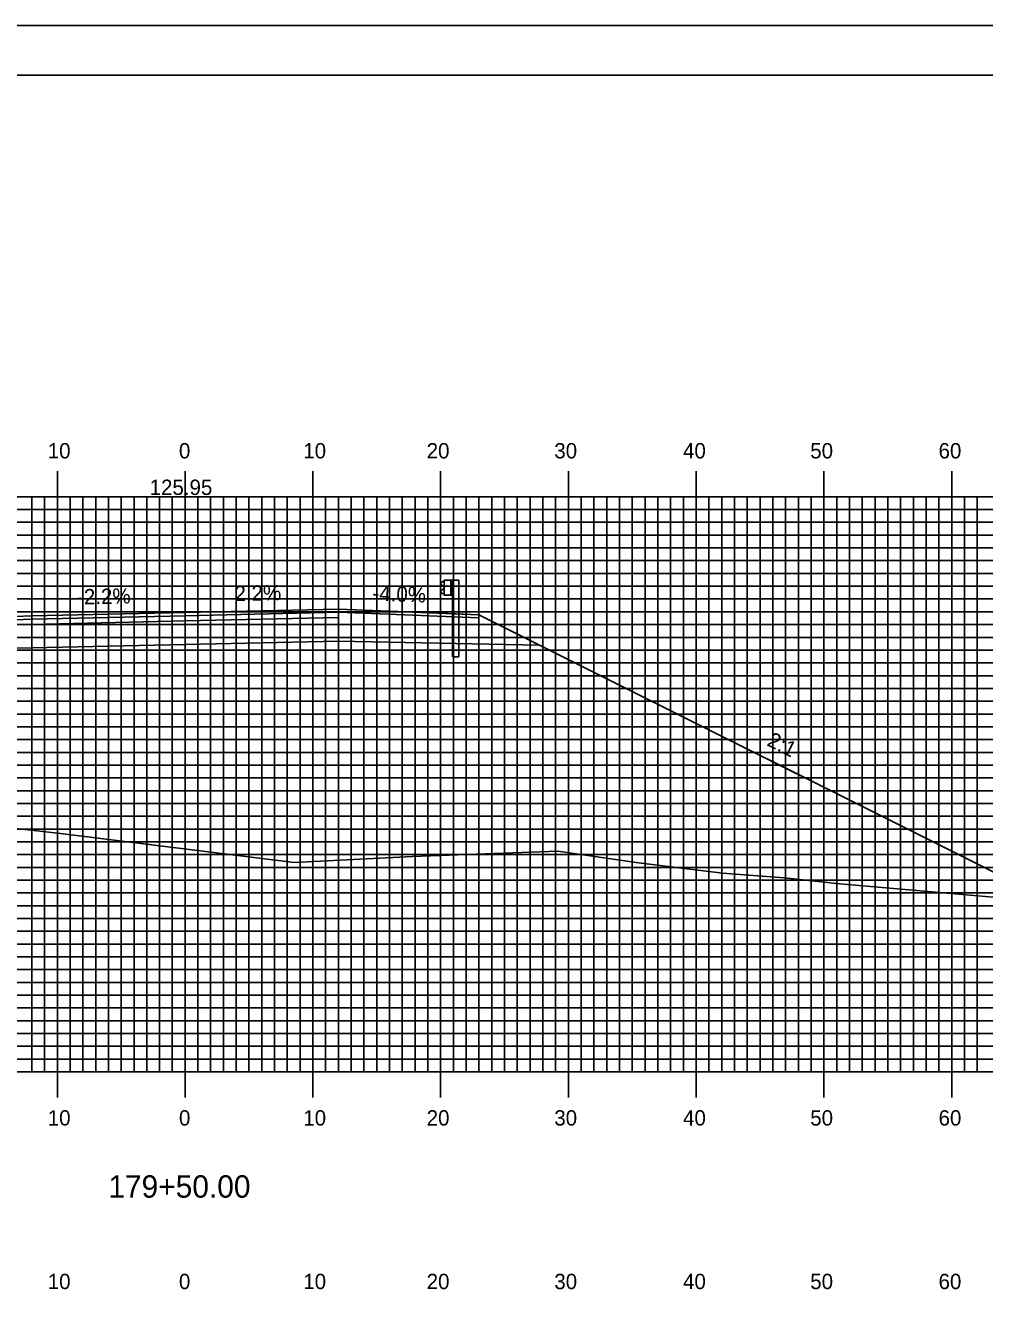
# Model space of a CAD drawing. Extents: x 1785402 to 1785745, y 442591 to 442811.
# Drawn here: x 1785555 to 1785630.1, y 442711.2 to 442810.5 of the extents above; entities that cross this region are included whole.
import ezdxf

# ---------------------------------------------------------------- set-up
doc = ezdxf.new("R2010")
doc.units = 0
for name, color, linetype in [('ANNOTATION', 7, 'Continuous'), ('BORDER', 7, 'Continuous'), ('D_Guardrail_Beam_Rt', 7, 'Continuous'), ('D_Roadway_Centerline', 7, 'Continuous'), ('D_Roadway_Centerline_Text', 7, 'Continuous'), ('D_Roadway_Edge_Shoulder', 7, 'Continuous'), ('D_Roadway_Edge_TW', 7, 'Continuous'), ('D_Roadway_Pavement', 7, 'Continuous'), ('D_Roadway_SlopeLines', 7, 'Continuous'), ('D_Roadway_SubGrade', 7, 'Continuous'), ('H_V ANNOTATION', 7, 'Continuous'), ('MAJOR', 7, 'Continuous'), ('MINOR', 7, 'Continuous'), ('PLOT BOUNDARY', 7, 'Continuous'), ('S_Roadway_Centerline', 7, 'Continuous')]:
    doc.layers.add(name, color=color, linetype=linetype)

msp = doc.modelspace()

# ---------------------------------------------------------------- linework, layer by layer
at = {"layer": 'BORDER'}
msp.add_lwpolyline([(1785417.939, 442596.665), (1785737.939, 442596.665), (1785737.939, 442806.665), (1785417.939, 442806.665)], close=True, dxfattribs=at)
at = {"layer": 'D_Guardrail_Beam_Rt'}
for p, q in [((1785587.72, 442767.033), (1785587.576, 442766.933)), ((1785587.576, 442766.79), (1785587.771, 442766.654)), ((1785587.809, 442767.054), (1785587.735, 442767.04)), ((1785587.809, 442767.138), (1785588.497, 442767.138)), ((1785587.809, 442765.971), (1785587.809, 442767.138)), ((1785588.33, 442767.138), (1785588.33, 442765.971)), ((1785588.434, 442767.138), (1785588.434, 442765.971)), ((1785588.497, 442767.138), (1785588.968, 442767.138)), ((1785588.497, 442767.138), (1785588.497, 442765.971)), ((1785588.968, 442767.138), (1785588.968, 442761.138)), ((1785587.771, 442766.455), (1785587.576, 442766.319)), ((1785587.576, 442766.176), (1785587.72, 442766.076)), ((1785587.735, 442766.069), (1785587.809, 442766.054)), ((1785587.805, 442766.589), (1785587.805, 442766.519)), ((1785588.497, 442765.971), (1785587.809, 442765.971)), ((1785588.476, 442761.138), (1785588.476, 442765.971)), ((1785588.476, 442761.138), (1785588.968, 442761.138))]:
    msp.add_line(p, q, dxfattribs=at)
for centre, major_axis, start_param, end_param in [((1785587.626, 442766.861), (-0.0877, 0), 5.323254, 7.243116), ((1785587.743, 442766.999), (-0.0417, 0), 4.907132, 5.323254), ((1785587.726, 442766.589), (0.0789, 0), 0, 0.959931), ((1785587.626, 442766.247), (-0.0877, 0), 5.323254, 7.243116), ((1785587.743, 442766.11), (-0.0417, 0), 0.959931, 1.376053), ((1785587.726, 442766.519), (0.0789, 0), 5.323254, 6.283185)]:
    msp.add_ellipse(centre, major_axis=major_axis, ratio=0.995501, start_param=start_param, end_param=end_param, dxfattribs=at)
at = {"layer": 'D_Roadway_Centerline'}
msp.add_lwpolyline([(1785504.216, 442750.585), (1785535.539, 442761.026), (1785537.365, 442761.483), (1785547.539, 442764.026), (1785555.539, 442764.346), (1785567.539, 442764.61), (1785579.539, 442764.874), (1785587.539, 442764.554), (1785590.539, 442764.434), (1785595.289, 442762.059), (1785635.591, 442741.908)], dxfattribs=at)
at = {"layer": 'D_Roadway_Edge_Shoulder'}
for points in [[(1785579.539, 442764.874), (1785587.539, 442764.554), (1785587.539, 442764.554), (1785590.539, 442764.434), (1785590.539, 442764.184), (1785579.539, 442764.624)], [(1785579.539, 442764.874), (1785590.539, 442764.434), (1785590.539, 442764.184), (1785579.539, 442764.624)], [(1785555.539, 442764.346), (1785547.539, 442764.026), (1785547.539, 442763.776), (1785555.539, 442764.096)]]:
    msp.add_lwpolyline(points, close=True, dxfattribs=at)
at = {"layer": 'D_Roadway_Edge_TW'}
msp.add_lwpolyline([(1785555.539, 442764.096), (1785555.539, 442764.346), (1785567.539, 442764.61), (1785579.539, 442764.874), (1785579.539, 442764.624), (1785567.539, 442764.36)], close=True, dxfattribs=at)
at = {"layer": 'D_Roadway_Pavement'}
msp.add_lwpolyline([(1785555.539, 442763.68), (1785555.539, 442764.096), (1785567.539, 442764.36), (1785579.539, 442764.624), (1785579.539, 442764.208), (1785567.539, 442763.944)], close=True, dxfattribs=at)
at = {"layer": 'D_Roadway_SlopeLines'}
msp.add_lwpolyline([(1785590.539, 442764.434), (1785635.591, 442741.908)], dxfattribs=at)
at = {"layer": 'D_Roadway_SubGrade'}
for points in [[(1785555.539, 442761.846), (1785537.365, 442761.483), (1785547.539, 442764.026), (1785547.539, 442763.776), (1785555.539, 442764.096), (1785567.539, 442764.36), (1785579.539, 442764.624), (1785590.539, 442764.184), (1785590.539, 442764.434), (1785595.289, 442762.059), (1785579.539, 442762.374), (1785567.539, 442762.11)], [(1785555.539, 442761.846), (1785537.365, 442761.483), (1785547.539, 442764.026), (1785547.539, 442763.776), (1785555.539, 442764.096)], [(1785555.539, 442761.846), (1785555.539, 442764.096), (1785567.539, 442764.36), (1785579.539, 442764.624), (1785579.539, 442762.374), (1785567.539, 442762.11)], [(1785579.539, 442764.624), (1785590.539, 442764.184), (1785590.539, 442764.434), (1785595.289, 442762.059), (1785579.539, 442762.374)]]:
    msp.add_lwpolyline(points, close=True, dxfattribs=at)
at = {"layer": 'MAJOR'}
for p, q in [((1785557.539, 442775.669), (1785557.539, 442773.665)), ((1785567.539, 442775.669), (1785567.539, 442773.665)), ((1785577.539, 442775.669), (1785577.539, 442773.665)), ((1785587.539, 442775.669), (1785587.539, 442773.665)), ((1785597.539, 442775.669), (1785597.539, 442773.665)), ((1785607.539, 442775.669), (1785607.539, 442773.665)), ((1785617.539, 442775.669), (1785617.539, 442773.665)), ((1785627.539, 442775.669), (1785627.539, 442773.665)), ((1785427.539, 442773.665), (1785707.539, 442773.665)), ((1785427.539, 442773.665), (1785707.539, 442773.665)), ((1785557.539, 442728.665), (1785557.539, 442773.665)), ((1785567.539, 442728.665), (1785567.539, 442773.665)), ((1785577.539, 442728.665), (1785577.539, 442773.665)), ((1785587.539, 442728.665), (1785587.539, 442773.665)), ((1785597.539, 442728.665), (1785597.539, 442773.665)), ((1785607.539, 442728.665), (1785607.539, 442773.665)), ((1785617.539, 442728.665), (1785617.539, 442773.665)), ((1785627.539, 442728.665), (1785627.539, 442773.665)), ((1785427.539, 442768.665), (1785707.539, 442768.665)), ((1785427.539, 442763.665), (1785707.539, 442763.665)), ((1785427.539, 442758.665), (1785707.539, 442758.665)), ((1785427.539, 442753.665), (1785707.539, 442753.665)), ((1785427.539, 442748.665), (1785707.539, 442748.665)), ((1785427.539, 442743.665), (1785707.539, 442743.665)), ((1785427.539, 442738.665), (1785707.539, 442738.665)), ((1785427.539, 442733.665), (1785707.539, 442733.665)), ((1785427.539, 442728.665), (1785707.539, 442728.665)), ((1785427.539, 442728.665), (1785707.539, 442728.665)), ((1785557.539, 442726.661), (1785557.539, 442728.665)), ((1785567.539, 442726.661), (1785567.539, 442728.665)), ((1785577.539, 442726.661), (1785577.539, 442728.665)), ((1785587.539, 442726.661), (1785587.539, 442728.665)), ((1785597.539, 442726.661), (1785597.539, 442728.665)), ((1785607.539, 442726.661), (1785607.539, 442728.665)), ((1785617.539, 442726.661), (1785617.539, 442728.665)), ((1785627.539, 442726.661), (1785627.539, 442728.665))]:
    msp.add_line(p, q, dxfattribs=at)
at = {"layer": 'MINOR'}
for p, q in [((1785555.539, 442728.665), (1785555.539, 442773.665)), ((1785556.539, 442728.665), (1785556.539, 442773.665)), ((1785558.539, 442728.665), (1785558.539, 442773.665)), ((1785559.539, 442728.665), (1785559.539, 442773.665)), ((1785560.539, 442728.665), (1785560.539, 442773.665)), ((1785561.539, 442728.665), (1785561.539, 442773.665)), ((1785562.539, 442728.665), (1785562.539, 442773.665)), ((1785563.539, 442728.665), (1785563.539, 442773.665)), ((1785564.539, 442728.665), (1785564.539, 442773.665)), ((1785565.539, 442728.665), (1785565.539, 442773.665)), ((1785566.539, 442728.665), (1785566.539, 442773.665)), ((1785568.539, 442728.665), (1785568.539, 442773.665)), ((1785569.539, 442728.665), (1785569.539, 442773.665)), ((1785570.539, 442728.665), (1785570.539, 442773.665)), ((1785571.539, 442728.665), (1785571.539, 442773.665)), ((1785572.539, 442728.665), (1785572.539, 442773.665)), ((1785573.539, 442728.665), (1785573.539, 442773.665)), ((1785574.539, 442728.665), (1785574.539, 442773.665)), ((1785575.539, 442728.665), (1785575.539, 442773.665)), ((1785576.539, 442728.665), (1785576.539, 442773.665)), ((1785578.539, 442728.665), (1785578.539, 442773.665)), ((1785579.539, 442728.665), (1785579.539, 442773.665)), ((1785580.539, 442728.665), (1785580.539, 442773.665)), ((1785581.539, 442728.665), (1785581.539, 442773.665)), ((1785582.539, 442728.665), (1785582.539, 442773.665)), ((1785583.539, 442728.665), (1785583.539, 442773.665)), ((1785584.539, 442728.665), (1785584.539, 442773.665)), ((1785585.539, 442728.665), (1785585.539, 442773.665)), ((1785586.539, 442728.665), (1785586.539, 442773.665)), ((1785588.539, 442728.665), (1785588.539, 442773.665)), ((1785589.539, 442728.665), (1785589.539, 442773.665)), ((1785590.539, 442728.665), (1785590.539, 442773.665)), ((1785591.539, 442728.665), (1785591.539, 442773.665)), ((1785592.539, 442728.665), (1785592.539, 442773.665)), ((1785593.539, 442728.665), (1785593.539, 442773.665)), ((1785594.539, 442728.665), (1785594.539, 442773.665)), ((1785595.539, 442728.665), (1785595.539, 442773.665)), ((1785596.539, 442728.665), (1785596.539, 442773.665)), ((1785598.539, 442728.665), (1785598.539, 442773.665)), ((1785599.539, 442728.665), (1785599.539, 442773.665)), ((1785600.539, 442728.665), (1785600.539, 442773.665)), ((1785601.539, 442728.665), (1785601.539, 442773.665)), ((1785602.539, 442728.665), (1785602.539, 442773.665)), ((1785603.539, 442728.665), (1785603.539, 442773.665)), ((1785604.539, 442728.665), (1785604.539, 442773.665)), ((1785605.539, 442728.665), (1785605.539, 442773.665)), ((1785606.539, 442728.665), (1785606.539, 442773.665)), ((1785608.539, 442728.665), (1785608.539, 442773.665)), ((1785609.539, 442728.665), (1785609.539, 442773.665)), ((1785610.539, 442728.665), (1785610.539, 442773.665)), ((1785611.539, 442728.665), (1785611.539, 442773.665)), ((1785612.539, 442728.665), (1785612.539, 442773.665)), ((1785613.539, 442728.665), (1785613.539, 442773.665)), ((1785614.539, 442728.665), (1785614.539, 442773.665)), ((1785615.539, 442728.665), (1785615.539, 442773.665)), ((1785616.539, 442728.665), (1785616.539, 442773.665)), ((1785618.539, 442728.665), (1785618.539, 442773.665)), ((1785619.539, 442728.665), (1785619.539, 442773.665)), ((1785620.539, 442728.665), (1785620.539, 442773.665)), ((1785621.539, 442728.665), (1785621.539, 442773.665)), ((1785622.539, 442728.665), (1785622.539, 442773.665)), ((1785623.539, 442728.665), (1785623.539, 442773.665)), ((1785624.539, 442728.665), (1785624.539, 442773.665)), ((1785625.539, 442728.665), (1785625.539, 442773.665)), ((1785626.539, 442728.665), (1785626.539, 442773.665)), ((1785628.539, 442728.665), (1785628.539, 442773.665)), ((1785629.539, 442728.665), (1785629.539, 442773.665)), ((1785427.539, 442772.665), (1785707.539, 442772.665)), ((1785427.539, 442771.665), (1785707.539, 442771.665)), ((1785427.539, 442770.665), (1785707.539, 442770.665)), ((1785427.539, 442769.665), (1785707.539, 442769.665)), ((1785427.539, 442767.665), (1785707.539, 442767.665)), ((1785427.539, 442766.665), (1785707.539, 442766.665)), ((1785427.539, 442765.665), (1785707.539, 442765.665)), ((1785427.539, 442764.665), (1785707.539, 442764.665)), ((1785427.539, 442762.665), (1785707.539, 442762.665)), ((1785427.539, 442761.665), (1785707.539, 442761.665)), ((1785427.539, 442760.665), (1785707.539, 442760.665)), ((1785427.539, 442759.665), (1785707.539, 442759.665)), ((1785427.539, 442757.665), (1785707.539, 442757.665)), ((1785427.539, 442756.665), (1785707.539, 442756.665)), ((1785427.539, 442755.665), (1785707.539, 442755.665)), ((1785427.539, 442754.665), (1785707.539, 442754.665)), ((1785427.539, 442752.665), (1785707.539, 442752.665)), ((1785427.539, 442751.665), (1785707.539, 442751.665)), ((1785427.539, 442750.665), (1785707.539, 442750.665)), ((1785427.539, 442749.665), (1785707.539, 442749.665)), ((1785427.539, 442747.665), (1785707.539, 442747.665)), ((1785427.539, 442746.665), (1785707.539, 442746.665)), ((1785427.539, 442745.665), (1785707.539, 442745.665)), ((1785427.539, 442744.665), (1785707.539, 442744.665)), ((1785427.539, 442742.665), (1785707.539, 442742.665)), ((1785427.539, 442741.665), (1785707.539, 442741.665)), ((1785427.539, 442740.665), (1785707.539, 442740.665)), ((1785427.539, 442739.665), (1785707.539, 442739.665)), ((1785427.539, 442737.665), (1785707.539, 442737.665)), ((1785427.539, 442736.665), (1785707.539, 442736.665)), ((1785427.539, 442735.665), (1785707.539, 442735.665)), ((1785427.539, 442734.665), (1785707.539, 442734.665)), ((1785427.539, 442732.665), (1785707.539, 442732.665)), ((1785427.539, 442731.665), (1785707.539, 442731.665)), ((1785427.539, 442730.665), (1785707.539, 442730.665)), ((1785427.539, 442729.665), (1785707.539, 442729.665))]:
    msp.add_line(p, q, dxfattribs=at)
at = {"layer": 'PLOT BOUNDARY'}
msp.add_lwpolyline([(1785401.752, 442590.547), (1785741.752, 442590.547), (1785741.752, 442810.547), (1785401.752, 442810.547)], close=True, dxfattribs=at)
at = {"layer": 'S_Roadway_Centerline'}
msp.add_lwpolyline([(1785497.706, 442750.905), (1785506.575, 442750.469), (1785512.661, 442750.14), (1785521.465, 442749.619), (1785532.678, 442749.687), (1785533.341, 442749.714), (1785533.78, 442749.676), (1785539.65, 442749.105), (1785555.021, 442747.639), (1785557.792, 442747.307), (1785576.069, 442745.047), (1785585.327, 442745.523), (1785596.7, 442745.925), (1785603.015, 442745.009), (1785609.594, 442744.22), (1785614.42, 442743.836), (1785618.773, 442743.37), (1785637.991, 442741.7)], dxfattribs=at)

# ---------------------------------------------------------------- texts
at = {"layer": 'ANNOTATION'}
for s, rotation, p in [('2.2%', 1.2603, (1785571.419, 442765.496)), ('-4.0%', 357.70939, (1785582.182, 442765.544)), ('-2.2%', 1.2603, (1785559.098, 442765.225)), ('2:1', 333.43495, (1785612.999, 442754.24))]:
    msp.add_text(s, height=1.2, rotation=rotation, dxfattribs=at).set_placement(p)
at = {"layer": 'D_Roadway_Centerline'}
for s, p in [('C', (1785567.533, 442764.61)), ('L', (1785567.539, 442764.603))]:
    msp.add_text(s, height=0.0146, dxfattribs=at).set_placement(p)
at = {"layer": 'D_Roadway_Centerline_Text'}
msp.add_text('125.95', height=1.2, dxfattribs=at).set_placement((1785564.761, 442773.806))
at = {"layer": 'H_V ANNOTATION'}
for s, height, p in [('10', 1.2, (1785556.789, 442776.665)), ('0', 1.2, (1785567.057, 442776.665)), ('10', 1.2, (1785576.789, 442776.665)), ('20', 1.2, (1785586.447, 442776.665)), ('30', 1.2, (1785596.436, 442776.665)), ('40', 1.2, (1785606.511, 442776.665)), ('50', 1.2, (1785616.468, 442776.665)), ('60', 1.2, (1785626.511, 442776.665)), ('10', 1.2, (1785556.789, 442724.465)), ('0', 1.2, (1785567.057, 442724.465)), ('10', 1.2, (1785576.789, 442724.465)), ('20', 1.2, (1785586.447, 442724.465)), ('30', 1.2, (1785596.436, 442724.465)), ('40', 1.2, (1785606.511, 442724.465)), ('50', 1.2, (1785616.468, 442724.465)), ('60', 1.2, (1785626.511, 442724.465)), ('179+50.00', 1.75, (1785561.53, 442718.821)), ('10', 1.2, (1785556.789, 442711.665)), ('0', 1.2, (1785567.057, 442711.665)), ('10', 1.2, (1785576.789, 442711.665)), ('20', 1.2, (1785586.447, 442711.665)), ('30', 1.2, (1785596.436, 442711.665)), ('40', 1.2, (1785606.511, 442711.665)), ('50', 1.2, (1785616.468, 442711.665)), ('60', 1.2, (1785626.511, 442711.665))]:
    msp.add_text(s, height=height, dxfattribs=at).set_placement(p)

doc.saveas('drawing.dxf')
